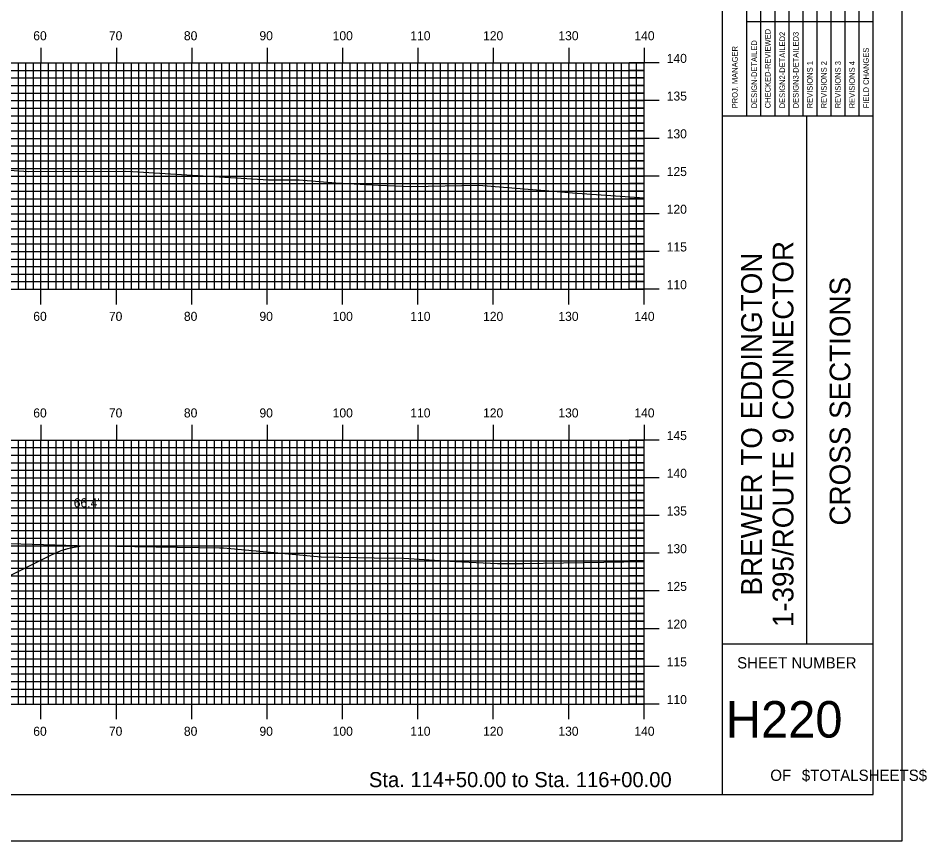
# Model space of a CAD drawing. Extents: x 1770842 to 1771185, y 442591 to 442811.
# Drawn here: x 1771064.5 to 1771185.1, y 442590.5 to 442699.6 of the extents above; entities that cross this region are included whole.
import ezdxf

# ---------------------------------------------------------------- set-up
doc = ezdxf.new("R2010")
doc.units = 0
for name, color, linetype in [('BORDER', 7, 'Continuous'), ('D_Roadway_Centerline', 7, 'Continuous'), ('D_Roadway_SlopeLines', 7, 'Continuous'), ('D_Text_Standard', 7, 'Continuous'), ('H_V ANNOTATION', 7, 'Continuous'), ('MAJOR', 7, 'Continuous'), ('MINOR', 7, 'Continuous'), ('PLOT BOUNDARY', 7, 'Continuous'), ('S_Roadway_Centerline', 7, 'Continuous')]:
    doc.layers.add(name, color=color, linetype=linetype)

msp = doc.modelspace()

# ---------------------------------------------------------------- linework, layer by layer
at = {"layer": 'BORDER'}
for p, q in [((1771157.95, 442596.67), (1771157.95, 442806.67)), ((1771157.95, 442686.67), (1771177.95, 442686.67)), ((1771169.14, 442616.67), (1771169.14, 442686.67)), ((1771157.95, 442616.67), (1771177.95, 442616.67))]:
    msp.add_line(p, q, dxfattribs=at)
msp.add_lwpolyline([(1770857.95, 442596.67), (1771177.95, 442596.67), (1771177.95, 442806.67), (1770857.95, 442806.67)], close=True, dxfattribs=at)
for points in [[(1771163.05, 442686.68), (1771163.05, 442721.67)], [(1771164.91, 442721.67), (1771164.91, 442686.68)], [(1771166.78, 442686.68), (1771166.78, 442721.67)], [(1771168.64, 442686.68), (1771168.64, 442721.67)], [(1771170.5, 442686.68), (1771170.5, 442721.67)], [(1771172.37, 442686.68), (1771172.37, 442721.67)], [(1771174.23, 442686.68), (1771174.23, 442721.67)], [(1771176.09, 442686.68), (1771176.09, 442721.67)], [(1771161.19, 442686.68), (1771161.19, 442720.26)], [(1771161.18, 442699.17), (1771177.95, 442699.17)]]:
    msp.add_lwpolyline(points, dxfattribs=at)
at = {"layer": 'D_Roadway_Centerline'}
msp.add_lwpolyline([(1771041.74, 442614.86), (1771068.97, 442628.47), (1771070.22, 442629.02), (1771071.1, 442629.28), (1771071.47, 442629.4), (1771072.64, 442629.6), (1771072.72, 442629.62), (1771072.75, 442629.62), (1771073.97, 442629.67)], dxfattribs=at)
at = {"layer": 'D_Roadway_SlopeLines'}
msp.add_lwpolyline([(1771041.73, 442614.85), (1771068.97, 442628.47), (1771070.22, 442629.02), (1771071.47, 442629.4), (1771072.72, 442629.62), (1771073.97, 442629.67)], dxfattribs=at)
at = {"layer": 'MAJOR'}
for p, q in [((1771067.55, 442695.67), (1771067.55, 442693.67)), ((1771077.55, 442695.67), (1771077.55, 442693.67)), ((1771087.55, 442695.67), (1771087.55, 442693.67)), ((1771097.55, 442695.67), (1771097.55, 442693.67)), ((1771107.55, 442695.67), (1771107.55, 442693.67)), ((1771117.55, 442695.67), (1771117.55, 442693.67)), ((1771127.55, 442695.67), (1771127.55, 442693.67)), ((1771137.55, 442695.67), (1771137.55, 442693.67)), ((1771147.55, 442695.67), (1771147.55, 442693.67)), ((1770867.55, 442693.67), (1771147.55, 442693.67)), ((1770867.55, 442693.67), (1771147.55, 442693.67)), ((1771067.55, 442663.67), (1771067.55, 442693.67)), ((1771077.55, 442663.67), (1771077.55, 442693.67)), ((1771087.55, 442663.67), (1771087.55, 442693.67)), ((1771097.55, 442663.67), (1771097.55, 442693.67)), ((1771107.55, 442663.67), (1771107.55, 442693.67)), ((1771117.55, 442663.67), (1771117.55, 442693.67)), ((1771127.55, 442663.67), (1771127.55, 442693.67)), ((1771137.55, 442663.67), (1771137.55, 442693.67)), ((1771149.56, 442693.67), (1771145.55, 442693.67)), ((1771147.55, 442663.67), (1771147.55, 442693.67)), ((1771147.55, 442663.67), (1771147.55, 442693.67)), ((1770867.55, 442688.67), (1771147.55, 442688.67)), ((1771149.56, 442688.67), (1771145.55, 442688.67)), ((1770867.55, 442683.67), (1771147.55, 442683.67)), ((1771149.56, 442683.67), (1771145.55, 442683.67)), ((1770867.55, 442678.67), (1771147.55, 442678.67)), ((1771149.56, 442678.67), (1771145.55, 442678.67)), ((1770867.55, 442673.67), (1771147.55, 442673.67)), ((1771149.56, 442673.67), (1771145.55, 442673.67)), ((1770867.55, 442668.67), (1771147.55, 442668.67)), ((1771149.56, 442668.67), (1771145.55, 442668.67)), ((1770867.55, 442663.67), (1771147.55, 442663.67)), ((1770867.55, 442663.67), (1771147.55, 442663.67)), ((1771067.55, 442661.66), (1771067.55, 442663.67)), ((1771077.55, 442661.66), (1771077.55, 442663.67)), ((1771087.55, 442661.66), (1771087.55, 442663.67)), ((1771097.55, 442661.66), (1771097.55, 442663.67)), ((1771107.55, 442661.66), (1771107.55, 442663.67)), ((1771117.55, 442661.66), (1771117.55, 442663.67)), ((1771127.55, 442661.66), (1771127.55, 442663.67)), ((1771137.55, 442661.66), (1771137.55, 442663.67)), ((1771149.56, 442663.67), (1771145.55, 442663.67)), ((1771147.55, 442661.66), (1771147.55, 442663.67)), ((1771067.55, 442645.67), (1771067.55, 442643.67)), ((1771077.55, 442645.67), (1771077.55, 442643.67)), ((1771087.55, 442645.67), (1771087.55, 442643.67)), ((1771097.55, 442645.67), (1771097.55, 442643.67)), ((1771107.55, 442645.67), (1771107.55, 442643.67)), ((1771117.55, 442645.67), (1771117.55, 442643.67)), ((1771127.55, 442645.67), (1771127.55, 442643.67)), ((1771137.55, 442645.67), (1771137.55, 442643.67)), ((1771147.55, 442645.67), (1771147.55, 442643.67)), ((1770867.55, 442643.67), (1771147.55, 442643.67)), ((1770867.55, 442643.67), (1771147.55, 442643.67)), ((1771067.55, 442608.67), (1771067.55, 442643.67)), ((1771077.55, 442608.67), (1771077.55, 442643.67)), ((1771087.55, 442608.67), (1771087.55, 442643.67)), ((1771097.55, 442608.67), (1771097.55, 442643.67)), ((1771107.55, 442608.67), (1771107.55, 442643.67)), ((1771117.55, 442608.67), (1771117.55, 442643.67)), ((1771127.55, 442608.67), (1771127.55, 442643.67)), ((1771137.55, 442608.67), (1771137.55, 442643.67)), ((1771149.56, 442643.67), (1771145.55, 442643.67)), ((1771147.55, 442608.67), (1771147.55, 442643.67)), ((1771147.55, 442608.67), (1771147.55, 442643.67)), ((1770867.55, 442638.67), (1771147.55, 442638.67)), ((1771149.56, 442638.67), (1771145.55, 442638.67)), ((1770867.55, 442633.67), (1771147.55, 442633.67)), ((1771149.56, 442633.67), (1771145.55, 442633.67)), ((1770867.55, 442628.67), (1771147.55, 442628.67)), ((1771149.56, 442628.67), (1771145.55, 442628.67)), ((1770867.55, 442623.67), (1771147.55, 442623.67)), ((1771149.56, 442623.67), (1771145.55, 442623.67)), ((1770867.55, 442618.67), (1771147.55, 442618.67)), ((1771149.56, 442618.67), (1771145.55, 442618.67)), ((1770867.55, 442613.67), (1771147.55, 442613.67)), ((1771149.56, 442613.67), (1771145.55, 442613.67)), ((1770867.55, 442608.67), (1771147.55, 442608.67)), ((1770867.55, 442608.67), (1771147.55, 442608.67)), ((1771067.55, 442606.66), (1771067.55, 442608.67)), ((1771077.55, 442606.66), (1771077.55, 442608.67)), ((1771087.55, 442606.66), (1771087.55, 442608.67)), ((1771097.55, 442606.66), (1771097.55, 442608.67)), ((1771107.55, 442606.66), (1771107.55, 442608.67)), ((1771117.55, 442606.66), (1771117.55, 442608.67)), ((1771127.55, 442606.66), (1771127.55, 442608.67)), ((1771137.55, 442606.66), (1771137.55, 442608.67)), ((1771149.56, 442608.67), (1771145.55, 442608.67)), ((1771147.55, 442606.66), (1771147.55, 442608.67))]:
    msp.add_line(p, q, dxfattribs=at)
at = {"layer": 'MINOR'}
for p, q in [((1771064.55, 442663.67), (1771064.55, 442693.67)), ((1771065.55, 442663.67), (1771065.55, 442693.67)), ((1771066.55, 442663.67), (1771066.55, 442693.67)), ((1771068.55, 442663.67), (1771068.55, 442693.67)), ((1771069.55, 442663.67), (1771069.55, 442693.67)), ((1771070.55, 442663.67), (1771070.55, 442693.67)), ((1771071.55, 442663.67), (1771071.55, 442693.67)), ((1771072.55, 442663.67), (1771072.55, 442693.67)), ((1771073.55, 442663.67), (1771073.55, 442693.67)), ((1771074.55, 442663.67), (1771074.55, 442693.67)), ((1771075.55, 442663.67), (1771075.55, 442693.67)), ((1771076.55, 442663.67), (1771076.55, 442693.67)), ((1771078.55, 442663.67), (1771078.55, 442693.67)), ((1771079.55, 442663.67), (1771079.55, 442693.67)), ((1771080.55, 442663.67), (1771080.55, 442693.67)), ((1771081.55, 442663.67), (1771081.55, 442693.67)), ((1771082.55, 442663.67), (1771082.55, 442693.67)), ((1771083.55, 442663.67), (1771083.55, 442693.67)), ((1771084.55, 442663.67), (1771084.55, 442693.67)), ((1771085.55, 442663.67), (1771085.55, 442693.67)), ((1771086.55, 442663.67), (1771086.55, 442693.67)), ((1771088.55, 442663.67), (1771088.55, 442693.67)), ((1771089.55, 442663.67), (1771089.55, 442693.67)), ((1771090.55, 442663.67), (1771090.55, 442693.67)), ((1771091.55, 442663.67), (1771091.55, 442693.67)), ((1771092.55, 442663.67), (1771092.55, 442693.67)), ((1771093.55, 442663.67), (1771093.55, 442693.67)), ((1771094.55, 442663.67), (1771094.55, 442693.67)), ((1771095.55, 442663.67), (1771095.55, 442693.67)), ((1771096.55, 442663.67), (1771096.55, 442693.67)), ((1771098.55, 442663.67), (1771098.55, 442693.67)), ((1771099.55, 442663.67), (1771099.55, 442693.67)), ((1771100.55, 442663.67), (1771100.55, 442693.67)), ((1771101.55, 442663.67), (1771101.55, 442693.67)), ((1771102.55, 442663.67), (1771102.55, 442693.67)), ((1771103.55, 442663.67), (1771103.55, 442693.67)), ((1771104.55, 442663.67), (1771104.55, 442693.67)), ((1771105.55, 442663.67), (1771105.55, 442693.67)), ((1771106.55, 442663.67), (1771106.55, 442693.67)), ((1771108.55, 442663.67), (1771108.55, 442693.67)), ((1771109.55, 442663.67), (1771109.55, 442693.67)), ((1771110.55, 442663.67), (1771110.55, 442693.67)), ((1771111.55, 442663.67), (1771111.55, 442693.67)), ((1771112.55, 442663.67), (1771112.55, 442693.67)), ((1771113.55, 442663.67), (1771113.55, 442693.67)), ((1771114.55, 442663.67), (1771114.55, 442693.67)), ((1771115.55, 442663.67), (1771115.55, 442693.67)), ((1771116.55, 442663.67), (1771116.55, 442693.67)), ((1771118.55, 442663.67), (1771118.55, 442693.67)), ((1771119.55, 442663.67), (1771119.55, 442693.67)), ((1771120.55, 442663.67), (1771120.55, 442693.67)), ((1771121.55, 442663.67), (1771121.55, 442693.67)), ((1771122.55, 442663.67), (1771122.55, 442693.67)), ((1771123.55, 442663.67), (1771123.55, 442693.67)), ((1771124.55, 442663.67), (1771124.55, 442693.67)), ((1771125.55, 442663.67), (1771125.55, 442693.67)), ((1771126.55, 442663.67), (1771126.55, 442693.67)), ((1771128.55, 442663.67), (1771128.55, 442693.67)), ((1771129.55, 442663.67), (1771129.55, 442693.67)), ((1771130.55, 442663.67), (1771130.55, 442693.67)), ((1771131.55, 442663.67), (1771131.55, 442693.67)), ((1771132.55, 442663.67), (1771132.55, 442693.67)), ((1771133.55, 442663.67), (1771133.55, 442693.67)), ((1771134.55, 442663.67), (1771134.55, 442693.67)), ((1771135.55, 442663.67), (1771135.55, 442693.67)), ((1771136.55, 442663.67), (1771136.55, 442693.67)), ((1771138.55, 442663.67), (1771138.55, 442693.67)), ((1771139.55, 442663.67), (1771139.55, 442693.67)), ((1771140.55, 442663.67), (1771140.55, 442693.67)), ((1771141.55, 442663.67), (1771141.55, 442693.67)), ((1771142.55, 442663.67), (1771142.55, 442693.67)), ((1771143.55, 442663.67), (1771143.55, 442693.67)), ((1771144.55, 442663.67), (1771144.55, 442693.67)), ((1771145.55, 442663.67), (1771145.55, 442693.67)), ((1771146.55, 442663.67), (1771146.55, 442693.67)), ((1770867.55, 442692.67), (1771147.55, 442692.67)), ((1771147.55, 442692.67), (1771145.55, 442692.67)), ((1770867.55, 442691.67), (1771147.55, 442691.67)), ((1770867.55, 442690.67), (1771147.55, 442690.67)), ((1771147.55, 442691.67), (1771145.55, 442691.67)), ((1771147.55, 442690.67), (1771145.55, 442690.67)), ((1770867.55, 442689.67), (1771147.55, 442689.67)), ((1771147.55, 442689.67), (1771145.55, 442689.67)), ((1770867.55, 442687.67), (1771147.55, 442687.67)), ((1771147.55, 442687.67), (1771145.55, 442687.67)), ((1770867.55, 442686.67), (1771147.55, 442686.67)), ((1771147.55, 442686.67), (1771145.55, 442686.67)), ((1770867.55, 442685.67), (1771147.55, 442685.67)), ((1770867.55, 442684.67), (1771147.55, 442684.67)), ((1771147.55, 442685.67), (1771145.55, 442685.67)), ((1771147.55, 442684.67), (1771145.55, 442684.67)), ((1770867.55, 442682.67), (1771147.55, 442682.67)), ((1771147.55, 442682.67), (1771145.55, 442682.67)), ((1770867.55, 442681.67), (1771147.55, 442681.67)), ((1771147.55, 442681.67), (1771145.55, 442681.67)), ((1770867.55, 442680.67), (1771147.55, 442680.67)), ((1771147.55, 442680.67), (1771145.55, 442680.67)), ((1770867.55, 442679.67), (1771147.55, 442679.67)), ((1771147.55, 442679.67), (1771145.55, 442679.67)), ((1770867.55, 442677.67), (1771147.55, 442677.67)), ((1771147.55, 442677.67), (1771145.55, 442677.67)), ((1770867.55, 442676.67), (1771147.55, 442676.67)), ((1771147.55, 442676.67), (1771145.55, 442676.67)), ((1770867.55, 442675.67), (1771147.55, 442675.67)), ((1771147.55, 442675.67), (1771145.55, 442675.67)), ((1770867.55, 442674.67), (1771147.55, 442674.67)), ((1771147.55, 442674.67), (1771145.55, 442674.67)), ((1770867.55, 442672.67), (1771147.55, 442672.67)), ((1771147.55, 442672.67), (1771145.55, 442672.67)), ((1770867.55, 442671.67), (1771147.55, 442671.67)), ((1771147.55, 442671.67), (1771145.55, 442671.67)), ((1770867.55, 442670.67), (1771147.55, 442670.67)), ((1771147.55, 442670.67), (1771145.55, 442670.67)), ((1770867.55, 442669.67), (1771147.55, 442669.67)), ((1771147.55, 442669.67), (1771145.55, 442669.67)), ((1770867.55, 442667.67), (1771147.55, 442667.67)), ((1770867.55, 442666.67), (1771147.55, 442666.67)), ((1771147.55, 442667.67), (1771145.55, 442667.67)), ((1771147.55, 442666.67), (1771145.55, 442666.67)), ((1770867.55, 442665.67), (1771147.55, 442665.67)), ((1771147.55, 442665.67), (1771145.55, 442665.67)), ((1770867.55, 442664.67), (1771147.55, 442664.67)), ((1771147.55, 442664.67), (1771145.55, 442664.67)), ((1771064.55, 442608.67), (1771064.55, 442643.67)), ((1771065.55, 442608.67), (1771065.55, 442643.67)), ((1771066.55, 442608.67), (1771066.55, 442643.67)), ((1771068.55, 442608.67), (1771068.55, 442643.67)), ((1771069.55, 442608.67), (1771069.55, 442643.67)), ((1771070.55, 442608.67), (1771070.55, 442643.67)), ((1771071.55, 442608.67), (1771071.55, 442643.67)), ((1771072.55, 442608.67), (1771072.55, 442643.67)), ((1771073.55, 442608.67), (1771073.55, 442643.67)), ((1771074.55, 442608.67), (1771074.55, 442643.67)), ((1771075.55, 442608.67), (1771075.55, 442643.67)), ((1771076.55, 442608.67), (1771076.55, 442643.67)), ((1771078.55, 442608.67), (1771078.55, 442643.67)), ((1771079.55, 442608.67), (1771079.55, 442643.67)), ((1771080.55, 442608.67), (1771080.55, 442643.67)), ((1771081.55, 442608.67), (1771081.55, 442643.67)), ((1771082.55, 442608.67), (1771082.55, 442643.67)), ((1771083.55, 442608.67), (1771083.55, 442643.67)), ((1771084.55, 442608.67), (1771084.55, 442643.67)), ((1771085.55, 442608.67), (1771085.55, 442643.67)), ((1771086.55, 442608.67), (1771086.55, 442643.67)), ((1771088.55, 442608.67), (1771088.55, 442643.67)), ((1771089.55, 442608.67), (1771089.55, 442643.67)), ((1771090.55, 442608.67), (1771090.55, 442643.67)), ((1771091.55, 442608.67), (1771091.55, 442643.67)), ((1771092.55, 442608.67), (1771092.55, 442643.67)), ((1771093.55, 442608.67), (1771093.55, 442643.67)), ((1771094.55, 442608.67), (1771094.55, 442643.67)), ((1771095.55, 442608.67), (1771095.55, 442643.67)), ((1771096.55, 442608.67), (1771096.55, 442643.67)), ((1771098.55, 442608.67), (1771098.55, 442643.67)), ((1771099.55, 442608.67), (1771099.55, 442643.67)), ((1771100.55, 442608.67), (1771100.55, 442643.67)), ((1771101.55, 442608.67), (1771101.55, 442643.67)), ((1771102.55, 442608.67), (1771102.55, 442643.67)), ((1771103.55, 442608.67), (1771103.55, 442643.67)), ((1771104.55, 442608.67), (1771104.55, 442643.67)), ((1771105.55, 442608.67), (1771105.55, 442643.67)), ((1771106.55, 442608.67), (1771106.55, 442643.67)), ((1771108.55, 442608.67), (1771108.55, 442643.67)), ((1771109.55, 442608.67), (1771109.55, 442643.67)), ((1771110.55, 442608.67), (1771110.55, 442643.67)), ((1771111.55, 442608.67), (1771111.55, 442643.67)), ((1771112.55, 442608.67), (1771112.55, 442643.67)), ((1771113.55, 442608.67), (1771113.55, 442643.67)), ((1771114.55, 442608.67), (1771114.55, 442643.67)), ((1771115.55, 442608.67), (1771115.55, 442643.67)), ((1771116.55, 442608.67), (1771116.55, 442643.67)), ((1771118.55, 442608.67), (1771118.55, 442643.67)), ((1771119.55, 442608.67), (1771119.55, 442643.67)), ((1771120.55, 442608.67), (1771120.55, 442643.67)), ((1771121.55, 442608.67), (1771121.55, 442643.67)), ((1771122.55, 442608.67), (1771122.55, 442643.67)), ((1771123.55, 442608.67), (1771123.55, 442643.67)), ((1771124.55, 442608.67), (1771124.55, 442643.67)), ((1771125.55, 442608.67), (1771125.55, 442643.67)), ((1771126.55, 442608.67), (1771126.55, 442643.67)), ((1771128.55, 442608.67), (1771128.55, 442643.67)), ((1771129.55, 442608.67), (1771129.55, 442643.67)), ((1771130.55, 442608.67), (1771130.55, 442643.67)), ((1771131.55, 442608.67), (1771131.55, 442643.67)), ((1771132.55, 442608.67), (1771132.55, 442643.67)), ((1771133.55, 442608.67), (1771133.55, 442643.67)), ((1771134.55, 442608.67), (1771134.55, 442643.67)), ((1771135.55, 442608.67), (1771135.55, 442643.67)), ((1771136.55, 442608.67), (1771136.55, 442643.67)), ((1771138.55, 442608.67), (1771138.55, 442643.67)), ((1771139.55, 442608.67), (1771139.55, 442643.67)), ((1771140.55, 442608.67), (1771140.55, 442643.67)), ((1771141.55, 442608.67), (1771141.55, 442643.67)), ((1771142.55, 442608.67), (1771142.55, 442643.67)), ((1771143.55, 442608.67), (1771143.55, 442643.67)), ((1771144.55, 442608.67), (1771144.55, 442643.67)), ((1771145.55, 442608.67), (1771145.55, 442643.67)), ((1771146.55, 442608.67), (1771146.55, 442643.67)), ((1770867.55, 442642.67), (1771147.55, 442642.67)), ((1771147.55, 442642.67), (1771145.55, 442642.67)), ((1770867.55, 442641.67), (1771147.55, 442641.67)), ((1771147.55, 442641.67), (1771145.55, 442641.67)), ((1770867.55, 442640.67), (1771147.55, 442640.67)), ((1771147.55, 442640.67), (1771145.55, 442640.67)), ((1770867.55, 442639.67), (1771147.55, 442639.67)), ((1771147.55, 442639.67), (1771145.55, 442639.67)), ((1770867.55, 442637.67), (1771147.55, 442637.67)), ((1771147.55, 442637.67), (1771145.55, 442637.67)), ((1770867.55, 442636.67), (1771147.55, 442636.67)), ((1771147.55, 442636.67), (1771145.55, 442636.67)), ((1770867.55, 442635.67), (1771147.55, 442635.67)), ((1771147.55, 442635.67), (1771145.55, 442635.67)), ((1770867.55, 442634.67), (1771147.55, 442634.67)), ((1771147.55, 442634.67), (1771145.55, 442634.67)), ((1770867.55, 442632.67), (1771147.55, 442632.67)), ((1770867.55, 442631.67), (1771147.55, 442631.67)), ((1771147.55, 442632.67), (1771145.55, 442632.67)), ((1771147.55, 442631.67), (1771145.55, 442631.67)), ((1770867.55, 442630.67), (1771147.55, 442630.67)), ((1771147.55, 442630.67), (1771145.55, 442630.67)), ((1770867.55, 442629.67), (1771147.55, 442629.67)), ((1771147.55, 442629.67), (1771145.55, 442629.67)), ((1770867.55, 442627.67), (1771147.55, 442627.67)), ((1771147.55, 442627.67), (1771145.55, 442627.67)), ((1770867.55, 442626.67), (1771147.55, 442626.67)), ((1770867.55, 442625.67), (1771147.55, 442625.67)), ((1771147.55, 442626.67), (1771145.55, 442626.67)), ((1771147.55, 442625.67), (1771145.55, 442625.67)), ((1770867.55, 442624.67), (1771147.55, 442624.67)), ((1771147.55, 442624.67), (1771145.55, 442624.67)), ((1770867.55, 442622.67), (1771147.55, 442622.67)), ((1771147.55, 442622.67), (1771145.55, 442622.67)), ((1770867.55, 442621.67), (1771147.55, 442621.67)), ((1770867.55, 442620.67), (1771147.55, 442620.67)), ((1771147.55, 442621.67), (1771145.55, 442621.67)), ((1771147.55, 442620.67), (1771145.55, 442620.67)), ((1770867.55, 442619.67), (1771147.55, 442619.67)), ((1771147.55, 442619.67), (1771145.55, 442619.67)), ((1770867.55, 442617.67), (1771147.55, 442617.67)), ((1771147.55, 442617.67), (1771145.55, 442617.67)), ((1770867.55, 442616.67), (1771147.55, 442616.67)), ((1771147.55, 442616.67), (1771145.55, 442616.67)), ((1770867.55, 442615.67), (1771147.55, 442615.67)), ((1770867.55, 442614.67), (1771147.55, 442614.67)), ((1771147.55, 442615.67), (1771145.55, 442615.67)), ((1771147.55, 442614.67), (1771145.55, 442614.67)), ((1770867.55, 442612.67), (1771147.55, 442612.67)), ((1771147.55, 442612.67), (1771145.55, 442612.67)), ((1770867.55, 442611.67), (1771147.55, 442611.67)), ((1771147.55, 442611.67), (1771145.55, 442611.67)), ((1770867.55, 442610.67), (1771147.55, 442610.67)), ((1771147.55, 442610.67), (1771145.55, 442610.67)), ((1770867.55, 442609.67), (1771147.55, 442609.67)), ((1771147.55, 442609.67), (1771145.55, 442609.67))]:
    msp.add_line(p, q, dxfattribs=at)
at = {"layer": 'PLOT BOUNDARY'}
msp.add_lwpolyline([(1770841.77, 442590.55), (1771181.77, 442590.55), (1771181.77, 442810.55), (1770841.77, 442810.55)], close=True, dxfattribs=at)
at = {"layer": 'S_Roadway_Centerline'}
for points in [[(1771047.93, 442680.53), (1771065.88, 442679.27), (1771078.7, 442679.33), (1771079.71, 442679.26), (1771097.75, 442678.18), (1771101.78, 442678.18), (1771106.67, 442677.79), (1771112.34, 442677.45), (1771116.65, 442677.3), (1771125.62, 442677.44), (1771136, 442676.62), (1771138.04, 442676.46), (1771147.55, 442675.77)], [(1771061.87, 442630), (1771072.36, 442629.7), (1771079.98, 442629.58), (1771091.21, 442629.4), (1771091.74, 442629.39), (1771104.71, 442628.19), (1771111.74, 442628.06), (1771115.68, 442628.03), (1771122.44, 442627.56), (1771128.09, 442627.31), (1771131.52, 442627.3), (1771147.55, 442627.56)]]:
    msp.add_lwpolyline(points, dxfattribs=at)

# ---------------------------------------------------------------- texts
at = {"layer": 'BORDER'}
for s, height, p in [('CHECKED-REVIEWED', 0.7455, (1771164.32, 442687.65)), ('DESIGN-DETAILED', 0.7455, (1771162.53, 442687.65)), ('DESIGN2-DETAILED2', 0.7455, (1771166.25, 442687.65)), ('DESIGN3-DETAILED3', 0.7455, (1771168.04, 442687.65)), ('PROJ. MANAGER', 0.7455, (1771159.96, 442687.65)), ('FIELD CHANGES', 0.7455, (1771177.36, 442687.65)), ('REVISIONS 1', 0.7455, (1771169.91, 442687.65)), ('REVISIONS 2', 0.7455, (1771171.77, 442687.65)), ('REVISIONS 3', 0.7455, (1771173.63, 442687.65)), ('REVISIONS 4', 0.7455, (1771175.5, 442687.65)), ('1-395/ROUTE 9 CONNECTOR', 2.7557, (1771167.36, 442618.87)), ('BREWER TO EDDINGTON', 2.7557, (1771163.18, 442623.07)), ('CROSS SECTIONS', 2.7557, (1771174.92, 442632.34))]:
    msp.add_text(s, height=height, rotation=90, dxfattribs=at).set_placement(p)
for s, height, p in [('SHEET NUMBER', 1.4905, (1771159.89, 442613.4)), ('H220', 4.839, (1771158.39, 442604.23)), ('OF', 1.491, (1771164.29, 442598.49)), ('$TOTALSHEETS$', 1.4905, (1771168.47, 442598.49))]:
    msp.add_text(s, height=height, dxfattribs=at).set_placement(p)
at = {"layer": 'D_Text_Standard'}
msp.add_text("66.4'", height=1.2, dxfattribs=at).set_placement((1771071.9, 442634.76))
at = {"layer": 'H_V ANNOTATION'}
for s, height, p in [('60', 1.2, (1771066.53, 442696.67)), ('70', 1.2, (1771076.56, 442696.67)), ('80', 1.2, (1771086.51, 442696.67)), ('90', 1.2, (1771096.53, 442696.67)), ('100', 1.2, (1771106.24, 442696.67)), ('110', 1.2, (1771116.54, 442696.67)), ('120', 1.2, (1771126.19, 442696.67)), ('130', 1.2, (1771136.18, 442696.67)), ('140', 1.2, (1771146.26, 442696.67)), ('140', 1.2, (1771150.55, 442693.67)), ('135', 1.2, (1771150.55, 442688.67)), ('130', 1.2, (1771150.55, 442683.67)), ('125', 1.2, (1771150.55, 442678.67)), ('120', 1.2, (1771150.55, 442673.67)), ('115', 1.2, (1771150.55, 442668.67)), ('110', 1.2, (1771150.55, 442663.67)), ('60', 1.2, (1771066.53, 442659.47)), ('70', 1.2, (1771076.56, 442659.47)), ('80', 1.2, (1771086.51, 442659.47)), ('90', 1.2, (1771096.53, 442659.47)), ('100', 1.2, (1771106.24, 442659.47)), ('110', 1.2, (1771116.54, 442659.47)), ('120', 1.2, (1771126.19, 442659.47)), ('130', 1.2, (1771136.18, 442659.47)), ('140', 1.2, (1771146.26, 442659.47)), ('60', 1.2, (1771066.53, 442646.67)), ('70', 1.2, (1771076.56, 442646.67)), ('80', 1.2, (1771086.51, 442646.67)), ('90', 1.2, (1771096.53, 442646.67)), ('100', 1.2, (1771106.24, 442646.67)), ('110', 1.2, (1771116.54, 442646.67)), ('120', 1.2, (1771126.19, 442646.67)), ('130', 1.2, (1771136.18, 442646.67)), ('140', 1.2, (1771146.26, 442646.67)), ('145', 1.2, (1771150.55, 442643.67)), ('140', 1.2, (1771150.55, 442638.67)), ('135', 1.2, (1771150.55, 442633.67)), ('130', 1.2, (1771150.55, 442628.67)), ('125', 1.2, (1771150.55, 442623.67)), ('120', 1.2, (1771150.55, 442618.67)), ('115', 1.2, (1771150.55, 442613.67)), ('110', 1.2, (1771150.55, 442608.67)), ('60', 1.2, (1771066.53, 442604.47)), ('70', 1.2, (1771076.56, 442604.47)), ('80', 1.2, (1771086.51, 442604.47)), ('90', 1.2, (1771096.53, 442604.47)), ('100', 1.2, (1771106.24, 442604.47)), ('110', 1.2, (1771116.54, 442604.47)), ('120', 1.2, (1771126.19, 442604.47)), ('130', 1.2, (1771136.18, 442604.47)), ('140', 1.2, (1771146.26, 442604.47)), ('Sta. 114+50.00 to Sta. 116+00.00', 2.0004, (1771111.05, 442597.66))]:
    msp.add_text(s, height=height, dxfattribs=at).set_placement(p)

doc.saveas('drawing.dxf')
